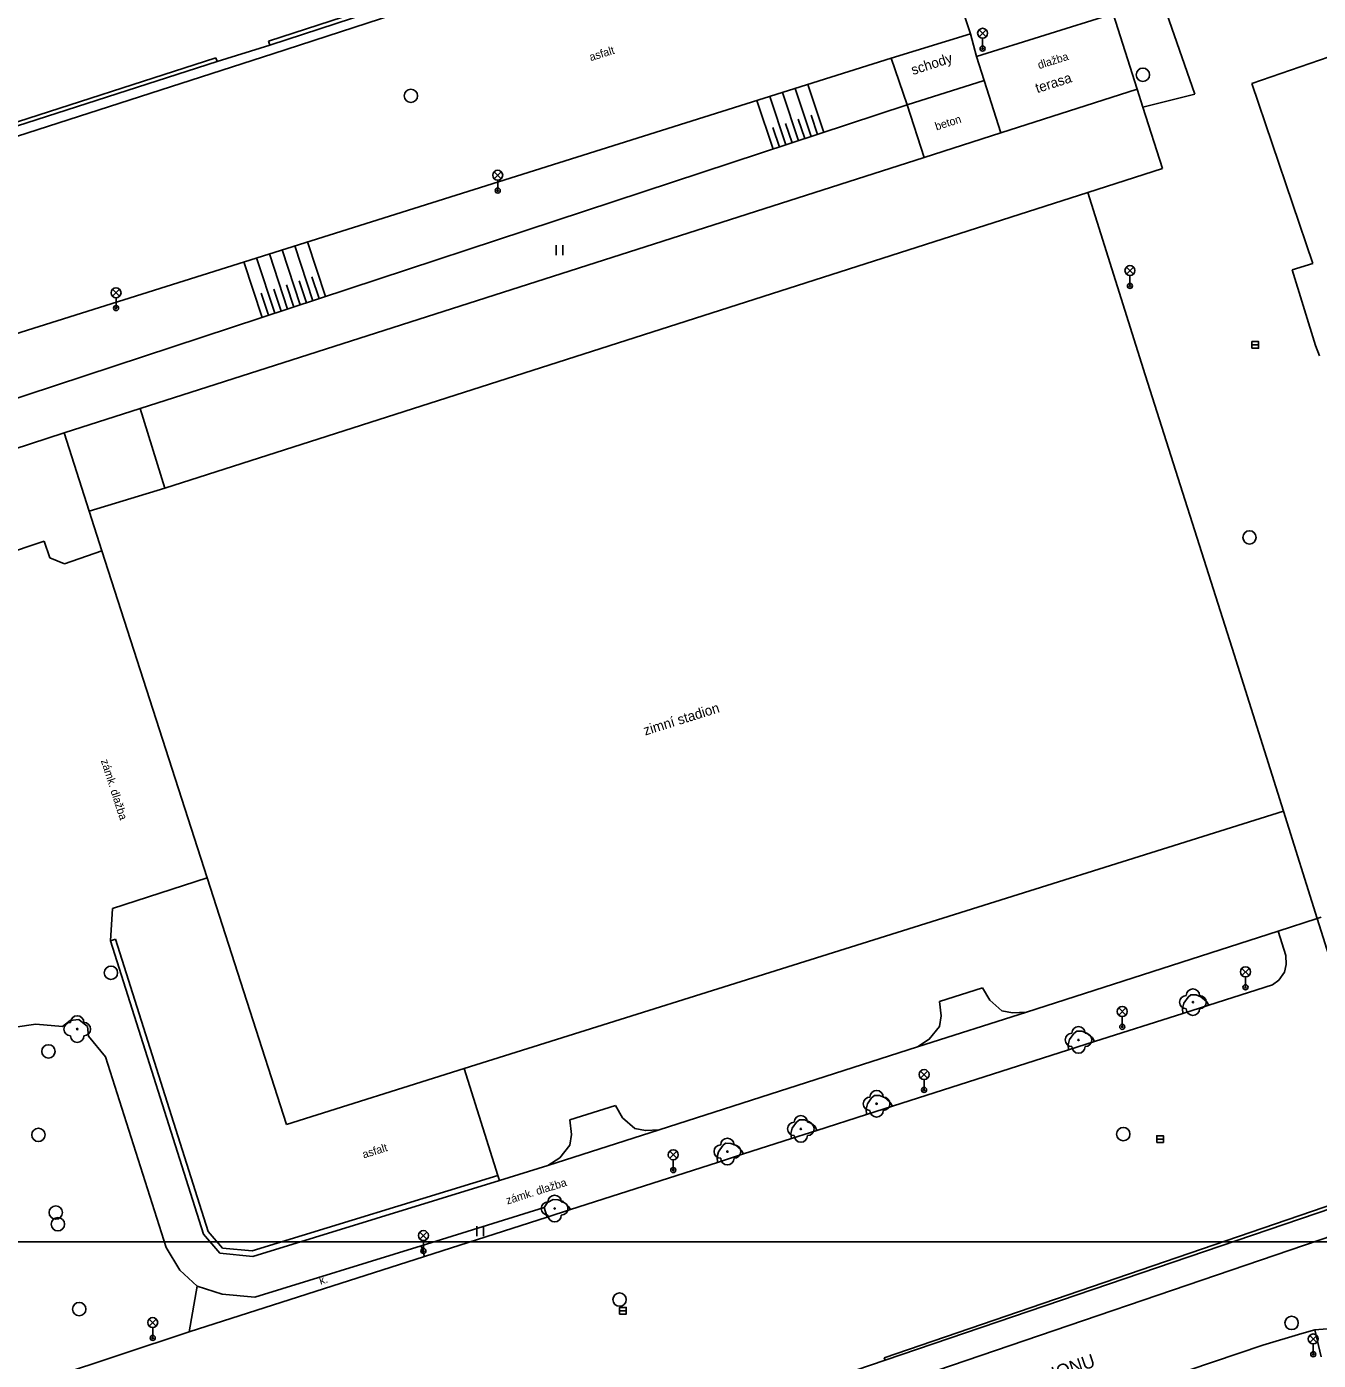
# Model space of a CAD drawing. Extents: x -493753 to -49290, y -1127285 to -112654.
# Drawn here: x -493243.7 to -493146.9, y -1127008.9 to -1126908.9 of the extents above; entities that cross this region are included whole.
import ezdxf

# ---------------------------------------------------------------- set-up
doc = ezdxf.new("R2010")
doc.units = 0
for name, color, linetype in [('Vrstva 10', 7, 'Continuous'), ('Vrstva 11', 7, 'Continuous'), ('Vrstva 14', 7, 'Continuous'), ('Vrstva 15', 7, 'Continuous'), ('Vrstva 22', 7, 'Continuous'), ('Vrstva 27', 7, 'Continuous'), ('Vrstva 33', 7, 'Continuous'), ('Vrstva 36', 7, 'Continuous'), ('Vrstva 40', 7, 'Continuous'), ('Vrstva 41', 7, 'Continuous'), ('Vrstva 42', 7, 'Continuous'), ('Vrstva 45', 7, 'Continuous'), ('Vrstva 5', 7, 'Continuous'), ('Vrstva 60', 7, 'Continuous'), ('Vrstva 7', 7, 'Continuous'), ('Vrstva 8', 7, 'Continuous')]:
    doc.layers.add(name, color=color, linetype=linetype)

msp = doc.modelspace()

# ---------------------------------------------------------------- linework, layer by layer
at = {"layer": 'Vrstva 10'}
for p, q in [((-493225.28, -1126910.96), (-493163.9, -1126890.92)), ((-493175.15, -1126902.75), (-493172.97, -1126909.46)), ((-493172.51, -1126911.16), (-493162.25, -1126907.94)), ((-493160.46, -1126913.61), (-493162.25, -1126907.94)), ((-493172.97, -1126909.46), (-493178.9, -1126911.27)), ((-493172.97, -1126909.46), (-493172.51, -1126911.16)), ((-493267.43, -1126924.51), (-493225.28, -1126910.96)), ((-493178.9, -1126911.27), (-493253.29, -1126934.68)), ((-493177.7, -1126914.78), (-493178.9, -1126911.27)), ((-493176.44, -1126918.73), (-493177.7, -1126914.78)), ((-493245.62, -1126948.55), (-493242.43, -1126947.48)), ((-493242.43, -1126947.48), (-493242, -1126948.73)), ((-493242, -1126948.73), (-493240.89, -1126949.19)), ((-493240.89, -1126949.19), (-493238.09, -1126948.2)), ((-493146.96, -1126975.76), (-493146.67, -1126975.67)), ((-493146.96, -1126975.76), (-493144.32, -1126984.2)), ((-493149.9, -1126976.71), (-493149.31, -1126978.54)), ((-493237.45, -1126977.45), (-493237.07, -1126977.33)), ((-493237.45, -1126977.45), (-493230.47, -1126999.44)), ((-493230.11, -1126999.24), (-493237.07, -1126977.33)), ((-493241.05, -1126983.87), (-493243.04, -1126983.68)), ((-493237.81, -1126986.13), (-493239.09, -1126984.58)), ((-493233.28, -1127000.43), (-493237.81, -1126986.13)), ((-493208.4, -1126995.04), (-493226.81, -1127000.69)), ((-493179.35, -1127008.88), (-493138.11, -1126994.84)), ((-493226.77, -1127001.1), (-493208.28, -1126995.42)), ((-493140.65, -1126995.42), (-493179.43, -1127008.71)), ((-493136.98, -1126996.52), (-493178.78, -1127010.77)), ((-493230.47, -1126999.44), (-493229.25, -1127000.86)), ((-493229.05, -1127000.48), (-493230.11, -1126999.24)), ((-493229.25, -1127000.86), (-493226.77, -1127001.1)), ((-493226.81, -1127000.69), (-493229.05, -1127000.48)), ((-493214.15, -1127000.3), (-493213.9, -1127001.1)), ((-493230.95, -1127003.33), (-493231.54, -1127006.75)), ((-493241.88, -1127010.17), (-493231.54, -1127006.75)), ((-493179.35, -1127008.88), (-493179.43, -1127008.71))]:
    msp.add_line(p, q, dxfattribs=at)
for points in [[(-493150.31, -1126980.73), (-493149.84, -1126980.39), (-493149.41, -1126979.79), (-493149.28, -1126979.23), (-493149.31, -1126978.54)], [(-493202.94, -1126997.59), (-493191.92, -1126994.05), (-493189.97, -1126993.42), (-493186.39, -1126992.27), (-493184.48, -1126991.66), (-493180.75, -1126990.47), (-493178.8, -1126989.84), (-493165.6, -1126985.62), (-493163.65, -1126985), (-493157.04, -1126982.88), (-493155.1, -1126982.26), (-493150.31, -1126980.73)], [(-493156.43, -1126981.49), (-493156.65, -1126981.66), (-493156.97, -1126982.12), (-493157.07, -1126982.51), (-493157.04, -1126982.88)], [(-493155.1, -1126982.26), (-493155.26, -1126982), (-493155.68, -1126981.64), (-493156.05, -1126981.5), (-493156.43, -1126981.49)], [(-493243.04, -1126983.68), (-493245.98, -1126984.12), (-493248.91, -1126984.68)], [(-493239.81, -1126983.34), (-493240.46, -1126983.42), (-493241.05, -1126983.87)], [(-493239.09, -1126984.58), (-493239.18, -1126983.87), (-493239.81, -1126983.34)], [(-493164.99, -1126984.21), (-493165.21, -1126984.38), (-493165.53, -1126984.84), (-493165.63, -1126985.23), (-493165.6, -1126985.62)], [(-493163.65, -1126985), (-493163.82, -1126984.72), (-493164.24, -1126984.36), (-493164.61, -1126984.22), (-493164.99, -1126984.21)], [(-493180.15, -1126989.04), (-493180.37, -1126989.21), (-493180.69, -1126989.67), (-493180.79, -1126990.06), (-493180.75, -1126990.47)], [(-493178.8, -1126989.84), (-493178.98, -1126989.55), (-493179.4, -1126989.19), (-493179.77, -1126989.05), (-493180.15, -1126989.04)], [(-493185.78, -1126990.86), (-493186, -1126991.03), (-493186.32, -1126991.49), (-493186.42, -1126991.88), (-493186.39, -1126992.27)], [(-493184.48, -1126991.66), (-493184.61, -1126991.37), (-493185.03, -1126991.01), (-493185.4, -1126990.87), (-493185.78, -1126990.86)], [(-493191.32, -1126992.62), (-493191.54, -1126992.79), (-493191.86, -1126993.25), (-493191.96, -1126993.64), (-493191.92, -1126994.05)], [(-493189.97, -1126993.42), (-493190.15, -1126993.13), (-493190.57, -1126992.77), (-493190.94, -1126992.63), (-493191.32, -1126992.62)], [(-493204.26, -1126996.84), (-493204.67, -1126997.07), (-493204.93, -1126997.44)], [(-493202.94, -1126997.59), (-493203.09, -1126997.35), (-493203.51, -1126996.99), (-493203.88, -1126996.85), (-493204.26, -1126996.84)], [(-493231.54, -1127006.75), (-493213.9, -1127001.1), (-493204.7, -1126998.15), (-493202.94, -1126997.59)], [(-493230.95, -1127003.33), (-493232.25, -1127002.13), (-493233.28, -1127000.43)], [(-493164.05, -1127012.15), (-493151.05, -1127007.76), (-493148.12, -1127006.88), (-493147.14, -1127006.61)], [(-493141.22, -1127007.32), (-493142.41, -1127006.79), (-493143.72, -1127006.52), (-493145.3, -1127006.45), (-493147.14, -1127006.61)], [(-493147.14, -1127006.61), (-493146.67, -1127008.62)]]:
    msp.add_lwpolyline(points, dxfattribs=at)
at = {"layer": 'Vrstva 11'}
for p, q in [((-493171.94, -1126912.94), (-493172.51, -1126911.16)), ((-493171.94, -1126912.94), (-493177.7, -1126914.78)), ((-493170.68, -1126916.88), (-493171.94, -1126912.94)), ((-493158.56, -1126919.55), (-493164.16, -1126921.34)), ((-493230.19, -1126972.73), (-493237.3, -1126975.01)), ((-493237.45, -1126977.45), (-493237.3, -1126975.01)), ((-493204.7, -1126998.15), (-493204.93, -1126997.44)), ((-493236.39, -1127028.17), (-493179.35, -1127008.88))]:
    msp.add_line(p, q, dxfattribs=at)
for points in [[(-493233.38, -1126943.51), (-493164.16, -1126921.34)], [(-493233.38, -1126943.51), (-493235.21, -1126937.54)], [(-493239.04, -1126945.24), (-493233.38, -1126943.51)], [(-493226.62, -1127004.16), (-493214.15, -1127000.3), (-493204.93, -1126997.44)], [(-493226.62, -1127004.16), (-493229.08, -1127003.93), (-493230.95, -1127003.33)]]:
    msp.add_lwpolyline(points, dxfattribs=at)
at = {"layer": 'Vrstva 14'}
msp.add_line((-493255.53, -1126940.41), (-493177.7, -1126914.78), dxfattribs=at)
at = {"layer": 'Vrstva 15'}
for p, q in [((-493186.81, -1126917.78), (-493188.01, -1126914.14)), ((-493185.86, -1126917.47), (-493187.06, -1126913.84)), ((-493184.91, -1126917.16), (-493186.1, -1126913.54)), ((-493183.96, -1126916.84), (-493185.15, -1126913.24)), ((-493187.76, -1126918.09), (-493188.97, -1126914.44)), ((-493186.34, -1126917.62), (-493186.82, -1126916.17)), ((-493185.39, -1126917.31), (-493185.87, -1126915.86)), ((-493184.44, -1126917), (-493184.91, -1126915.55)), ((-493187.29, -1126917.94), (-493187.77, -1126916.48)), ((-493221.32, -1126929.15), (-493222.67, -1126925.04)), ((-493224.17, -1126930.08), (-493225.53, -1126925.95)), ((-493223.22, -1126929.77), (-493224.58, -1126925.65)), ((-493222.27, -1126929.46), (-493223.62, -1126925.34)), ((-493226.07, -1126930.71), (-493227.44, -1126926.55)), ((-493225.12, -1126930.4), (-493226.49, -1126926.25)), ((-493222.75, -1126929.61), (-493223.29, -1126927.97)), ((-493221.8, -1126929.3), (-493222.34, -1126927.66)), ((-493225.6, -1126930.55), (-493226.14, -1126928.89)), ((-493224.65, -1126930.24), (-493225.19, -1126928.58)), ((-493223.7, -1126929.93), (-493224.24, -1126928.27))]:
    msp.add_line(p, q, dxfattribs=at)
at = {"layer": 'Vrstva 22'}
for centre in [(-493156.28, -1126982.04), (-493239.94, -1126984.06), (-493164.86, -1126984.87), (-493180, -1126989.66), (-493185.68, -1126991.54), (-493191.19, -1126993.24), (-493204.14, -1126997.51)]:
    msp.add_circle(centre, 0.05, dxfattribs=at)
for centre, start, end in [((-493156.28, -1126981.54), 0, 180), ((-493156.78, -1126982.04), 90, 270), ((-493155.78, -1126982.04), 270, 90), ((-493239.94, -1126983.56), 0, 180), ((-493156.28, -1126982.54), 180, 0), ((-493240.44, -1126984.06), 90, 270), ((-493239.44, -1126984.06), 270, 90), ((-493164.86, -1126984.37), 0, 180), ((-493239.94, -1126984.56), 180, 0), ((-493165.36, -1126984.87), 90, 270), ((-493164.36, -1126984.87), 270, 90), ((-493164.86, -1126985.37), 180, 0), ((-493180.5, -1126989.66), 90, 270), ((-493180, -1126989.16), 0, 180), ((-493179.5, -1126989.66), 270, 90), ((-493180, -1126990.16), 180, 0), ((-493186.18, -1126991.54), 90, 270), ((-493185.68, -1126991.04), 0, 180), ((-493185.18, -1126991.54), 270, 90), ((-493185.68, -1126992.04), 180, 0), ((-493191.69, -1126993.24), 90, 270), ((-493191.19, -1126992.74), 0, 180), ((-493190.69, -1126993.24), 270, 90), ((-493191.19, -1126993.74), 180, 0), ((-493204.64, -1126997.51), 90, 270), ((-493204.14, -1126997.01), 0, 180), ((-493203.64, -1126997.51), 270, 90), ((-493204.14, -1126998.01), 180, 0)]:
    msp.add_arc(centre, 0.5, start, end, dxfattribs=at)
at = {"layer": 'Vrstva 27'}
for p, q in [((-493151.86, -1126932.77), (-493151.36, -1126932.77)), ((-493158.99, -1126992.3), (-493158.49, -1126992.3)), ((-493199.27, -1127005.17), (-493198.77, -1127005.17))]:
    msp.add_line(p, q, dxfattribs=at)
for points in [[(-493151.86, -1126933.02), (-493151.36, -1126933.02), (-493151.36, -1126932.52), (-493151.86, -1126932.52)], [(-493158.99, -1126992.55), (-493158.49, -1126992.55), (-493158.49, -1126992.05), (-493158.99, -1126992.05)], [(-493199.27, -1127005.42), (-493198.77, -1127005.42), (-493198.77, -1127004.92), (-493199.27, -1127004.92)]]:
    msp.add_lwpolyline(points, close=True, dxfattribs=at)
for centre in [(-493160.03, -1126912.52), (-493214.92, -1126914.1), (-493152.04, -1126947.2), (-493237.41, -1126979.84), (-493242.1, -1126985.73), (-493242.85, -1126991.99), (-493161.5, -1126991.93), (-493241.55, -1126997.81), (-493241.39, -1126998.69), (-493199.27, -1127004.34), (-493239.79, -1127005.05), (-493148.88, -1127006.09)]:
    msp.add_circle(centre, 0.5, dxfattribs=at)
at = {"layer": 'Vrstva 33'}
for p, q in [((-493172.315, -1126909.145), (-493171.785, -1126909.675)), ((-493172.315, -1126909.675), (-493171.785, -1126909.145)), ((-493172.05, -1126910.56), (-493172.05, -1126909.785)), ((-493208.675, -1126919.785), (-493208.145, -1126920.315)), ((-493208.675, -1126920.315), (-493208.145, -1126919.785)), ((-493208.41, -1126921.2), (-493208.41, -1126920.425)), ((-493161.265, -1126926.935), (-493160.735, -1126927.465)), ((-493161.265, -1126927.465), (-493160.735, -1126926.935)), ((-493161, -1126928.35), (-493161, -1126927.575)), ((-493237.295, -1126928.595), (-493236.765, -1126929.125)), ((-493237.295, -1126929.125), (-493236.765, -1126928.595)), ((-493237.03, -1126930.01), (-493237.03, -1126929.235)), ((-493152.605, -1126979.505), (-493152.075, -1126980.035)), ((-493152.605, -1126980.035), (-493152.075, -1126979.505)), ((-493152.34, -1126980.92), (-493152.34, -1126980.145)), ((-493161.845, -1126982.475), (-493161.315, -1126983.005)), ((-493161.845, -1126983.005), (-493161.315, -1126982.475)), ((-493161.58, -1126983.89), (-493161.58, -1126983.115)), ((-493176.705, -1126987.205), (-493176.175, -1126987.735)), ((-493176.705, -1126987.735), (-493176.175, -1126987.205)), ((-493176.44, -1126988.62), (-493176.44, -1126987.845)), ((-493195.515, -1126993.215), (-493194.985, -1126993.745)), ((-493195.515, -1126993.745), (-493194.985, -1126993.215)), ((-493195.25, -1126994.63), (-493195.25, -1126993.855)), ((-493214.245, -1126999.275), (-493213.715, -1126999.805)), ((-493214.245, -1126999.805), (-493213.715, -1126999.275)), ((-493213.98, -1127000.69), (-493213.98, -1126999.915)), ((-493234.545, -1127005.795), (-493234.015, -1127006.325)), ((-493234.545, -1127006.325), (-493234.015, -1127005.795)), ((-493234.28, -1127007.21), (-493234.28, -1127006.435)), ((-493147.525, -1127007.025), (-493146.995, -1127007.555)), ((-493147.525, -1127007.555), (-493146.995, -1127007.025)), ((-493147.26, -1127008.44), (-493147.26, -1127007.665))]:
    msp.add_line(p, q, dxfattribs=at)
for centre, radius in [((-493172.05, -1126909.41), 0.375), ((-493172.05, -1126910.56), 0.19), ((-493172.05, -1126910.56), 0.05), ((-493208.41, -1126920.05), 0.375), ((-493208.41, -1126921.2), 0.19), ((-493208.41, -1126921.2), 0.05), ((-493161, -1126927.2), 0.375), ((-493161, -1126928.35), 0.19), ((-493237.03, -1126928.86), 0.375), ((-493161, -1126928.35), 0.05), ((-493237.03, -1126930.01), 0.19), ((-493237.03, -1126930.01), 0.05), ((-493152.34, -1126979.77), 0.375), ((-493152.34, -1126980.92), 0.19), ((-493152.34, -1126980.92), 0.05), ((-493161.58, -1126982.74), 0.375), ((-493161.58, -1126983.89), 0.19), ((-493161.58, -1126983.89), 0.05), ((-493176.44, -1126987.47), 0.375), ((-493176.44, -1126988.62), 0.19), ((-493176.44, -1126988.62), 0.05), ((-493195.25, -1126993.48), 0.375), ((-493195.25, -1126994.63), 0.19), ((-493195.25, -1126994.63), 0.05), ((-493213.98, -1126999.54), 0.375), ((-493213.98, -1127000.69), 0.19), ((-493213.98, -1127000.69), 0.05), ((-493234.28, -1127006.06), 0.375), ((-493234.28, -1127007.21), 0.19), ((-493234.28, -1127007.21), 0.05), ((-493147.26, -1127007.29), 0.375), ((-493147.26, -1127008.44), 0.19), ((-493147.26, -1127008.44), 0.05)]:
    msp.add_circle(centre, radius, dxfattribs=at)
at = {"layer": 'Vrstva 36'}
for p, q in [((-493204.02, -1126926.04), (-493204.02, -1126925.29)), ((-493203.52, -1126926.04), (-493203.52, -1126925.29)), ((-493209.97, -1126999.58), (-493209.97, -1126998.83)), ((-493209.47, -1126999.58), (-493209.47, -1126998.83))]:
    msp.add_line(p, q, dxfattribs=at)
at = {"layer": 'Vrstva 5'}
for p, q in [((-493151.87, -1126913.18), (-493132.83, -1126906.59)), ((-493147.3, -1126926.67), (-493151.87, -1126913.18)), ((-493147.3, -1126926.67), (-493148.85, -1126927.15)), ((-493147.08, -1126932.82), (-493148.85, -1126927.15)), ((-493146.8, -1126933.6), (-493147.08, -1126932.82)), ((-493159.86, -1126935.01), (-493153.34, -1126955.5)), ((-493153.34, -1126955.5), (-493149.49, -1126967.72)), ((-493146.96, -1126975.76), (-493149.49, -1126967.72)), ((-493172.05, -1126980.96), (-493175.28, -1126981.98)), ((-493176.94, -1126985.39), (-493168.77, -1126982.78)), ((-493196.3, -1126991.6), (-493176.94, -1126985.39)), ((-493202.99, -1126990.87), (-493199.58, -1126989.78)), ((-493204.65, -1126994.28), (-493196.3, -1126991.6)), ((-493208.28, -1126995.42), (-493204.65, -1126994.28))]:
    msp.add_line(p, q, dxfattribs=at)
for points in [[(-493160.46, -1126913.61), (-493170.68, -1126916.88), (-493176.44, -1126918.73), (-493235.21, -1126937.54), (-493240.93, -1126939.37)], [(-493158.56, -1126919.55), (-493160.03, -1126914.95), (-493160.46, -1126913.61)], [(-493164.16, -1126921.34), (-493159.86, -1126935.01)], [(-493224.24, -1126991.21), (-493230.19, -1126972.73), (-493238.09, -1126948.2), (-493239.04, -1126945.24), (-493240.93, -1126939.37)], [(-493149.49, -1126967.72), (-493210.92, -1126987.02)], [(-493168.77, -1126982.78), (-493149.9, -1126976.71), (-493146.96, -1126975.76)], [(-493168.77, -1126982.78), (-493169.8, -1126982.85), (-493170.61, -1126982.68), (-493171.52, -1126981.88), (-493172.05, -1126980.96)], [(-493175.28, -1126981.98), (-493175.16, -1126983.06), (-493175.29, -1126983.87), (-493176.05, -1126984.82), (-493176.94, -1126985.39)], [(-493210.92, -1126987.02), (-493224.24, -1126991.21)], [(-493210.92, -1126987.02), (-493208.4, -1126995.04), (-493208.28, -1126995.42)], [(-493196.3, -1126991.6), (-493197.33, -1126991.67), (-493198.14, -1126991.5), (-493199.05, -1126990.7), (-493199.58, -1126989.78)], [(-493202.99, -1126990.87), (-493202.87, -1126991.95), (-493203, -1126992.76), (-493203.76, -1126993.71), (-493204.65, -1126994.28)]]:
    msp.add_lwpolyline(points, dxfattribs=at)
at = {"layer": 'Vrstva 60'}
for points in [[(-493659.148, -1127000), (-493125, -1127000), (-493125, -1126587.478)], [(-493125, -1127069.371), (-493125, -1127000), (-493659.148, -1127000)]]:
    msp.add_lwpolyline(points, dxfattribs=at)
at = {"layer": 'Vrstva 7'}
for p, q in [((-493165.44, -1126890.38), (-493225.59, -1126910.01)), ((-493225.5, -1126910.29), (-493165.35, -1126890.66)), ((-493156.13, -1126913.98), (-493158.63, -1126906.77)), ((-493225.5, -1126910.29), (-493225.59, -1126910.01)), ((-493229.54, -1126911.24), (-493267.39, -1126923.44)), ((-493267.3, -1126923.73), (-493229.45, -1126911.53)), ((-493229.45, -1126911.53), (-493229.54, -1126911.24)), ((-493156.13, -1126913.98), (-493160.03, -1126914.95)), ((-493258.41, -1126945.03), (-493240.93, -1126939.37))]:
    msp.add_line(p, q, dxfattribs=at)
at = {"layer": 'Vrstva 8'}
msp.add_line((-493229.45, -1126911.53), (-493225.5, -1126910.29), dxfattribs=at)

# ---------------------------------------------------------------- texts
at = {"layer": 'Vrstva 40'}
for s, rotation, p in [('asfalt', 17.46842, (-493201.43, -1126911.502)), ('dlažba', 17.46842, (-493167.811, -1126912.1)), ('beton', 17.46842, (-493175.512, -1126916.693)), ('zámk. dlažba', 287.84608, (-493238.173, -1126963.939)), ('asfalt', 17.44519, (-493218.451, -1126993.762)), ('zámk. dlažba', 17.46642, (-493207.687, -1126997.216)), ('k.', 17.75921, (-493221.691, -1127003.23))]:
    msp.add_text(s, height=0.6, rotation=rotation, dxfattribs=at).set_placement(p)
at = {"layer": 'Vrstva 41'}
msp.add_text('zimní stadion', height=0.75, rotation=17.44519, dxfattribs=at).set_placement((-493197.35, -1126962.058))
at = {"layer": 'Vrstva 42'}
for s, rotation, p in [('schody', 17.75478, (-493177.27, -1126912.543)), ('terasa', 17.75087, (-493167.956, -1126913.904))]:
    msp.add_text(s, height=0.75, rotation=rotation, dxfattribs=at).set_placement(p)
at = {"layer": 'Vrstva 45'}
msp.add_text('U STADIONU', height=1, rotation=18.65943, dxfattribs=at).set_placement((-493171.336, -1127011.967))

doc.saveas('drawing.dxf')
